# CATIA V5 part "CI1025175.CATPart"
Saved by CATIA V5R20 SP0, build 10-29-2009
Part number: CI1025175
Bounding box of the stored display mesh (mm): x -24 to 24, y -20.11 to 209.5, z -26.352 to 28.386
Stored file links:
  C:\Users\Raffaele\Desktop\3D X SITO CF\BOLEX\19-INCLINED ASSEMBLY REF_CI\CI1025175.CATPart
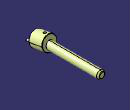
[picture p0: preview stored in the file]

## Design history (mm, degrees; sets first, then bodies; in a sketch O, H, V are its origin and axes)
Set1
  DatumSurface1 to DatumSurface16 "MANIFOLD_SOLID_BREP #393"
  DatumSurface17 to DatumSurface39 "MANIFOLD_SOLID_BREP #1138"
Body1 (main body)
